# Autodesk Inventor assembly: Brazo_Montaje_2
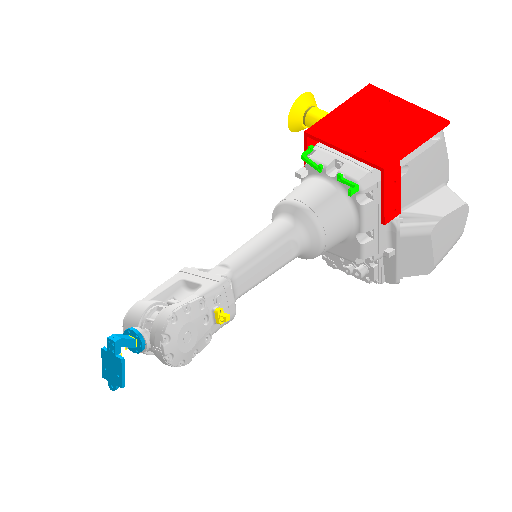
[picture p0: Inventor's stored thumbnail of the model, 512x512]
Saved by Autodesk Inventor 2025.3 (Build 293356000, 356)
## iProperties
Created: 2014-11
Part Number: Brazo_Montaje_2
Description: STEP AP203
Document SubType Name: Assembly
Designer: Dell
Sending System: SolidWorks 2012
Preprocessor: SwSTEP 2.0
Title: IRB 2600 12-1,85.STEP
Author: Jaanus
Revision Number: ANY
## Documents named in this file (11)
- C:\Users\Dell\Downloads\Tesis 2.0\CAD Final\Brazo_Montaje_2.iam
- C:\Users\Dell\Downloads\IRB 2600 12-1,85\IRB 2600 12-1,85\Link3L.ipt
- C:\Users\Dell\Downloads\IRB 2600 12-1,85\IRB 2600 12-1,85\Link4L_02.ipt
- C:\Users\Dell\Downloads\IRB 2600 12-1,85\IRB 2600 12-1,85\Link5L_02.ipt
- C:\Users\Dell\Downloads\IRB 2600 12-1,85\IRB 2600 12-1,85\Link6L.ipt
- C:\Users\Dell\Downloads\Tesis 2.0\CAD Final\Acople_Cable.ipt
- C:\Users\Dell\Downloads\Tesis 2.0\CAD Final\Acople_PLA.ipt
- C:\Users\Dell\Downloads\Tesis 2.0\CAD Final\Tapa_Carrete.ipt
- C:\Users\Dell\Downloads\Tesis 2.0\Pieza Final Arduino_2.ipt
- C:\Users\Dell\Downloads\Tapa_Carrete.ipt
- C:\Users\Dell\Downloads\Tesis 2.0\Pieza_FINAL_EXTRUSOR.iam
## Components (11 placed, 9 different names)
1. Link3L_4 — Insertar:3, Insertar:4, Insertar:5, Insertar:8, Insertar:9
2. Link4L_02_5 — Insertar:1, Insertar:2
3. Link5L_02_6
4. Link6L_11 — Insertar:10
5. Acople_Cable:1 — Insertar:1, Insertar:2
6. Acople_PLA:1 — Insertar:6, Insertar:7
7. Tapa_Carrete:1 — Insertar:7
8. Pieza Final Arduino_2:1 — Insertar:3, Insertar:4, Insertar:5, Insertar:6
9. Tapa_Carrete:2 — Insertar:9
10. Tapa_Carrete:3 — Insertar:8
11. Pieza_FINAL_EXTRUSOR:1 [sub-assembly] — Insertar:10
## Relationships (10: Insert 10)
- Insertar:1: Link4L_02_5 ↔ Acople_Cable:1
- Insertar:2: Link4L_02_5 ↔ Acople_Cable:1
- Insertar:3: Link3L_4 ↔ Pieza Final Arduino_2:1
- Insertar:4: Link3L_4 ↔ Pieza Final Arduino_2:1
- Insertar:5: Link3L_4 ↔ Pieza Final Arduino_2:1
- Insertar:6: Acople_PLA:1 ↔ Pieza Final Arduino_2:1
- Insertar:7: Acople_PLA:1 ↔ Tapa_Carrete:1
- Insertar:8: Link3L_4 ↔ Tapa_Carrete:3
- Insertar:9: Link3L_4 ↔ Tapa_Carrete:2
- Insertar:10: Link6L_11 ↔ Pieza_FINAL_EXTRUSOR:1
